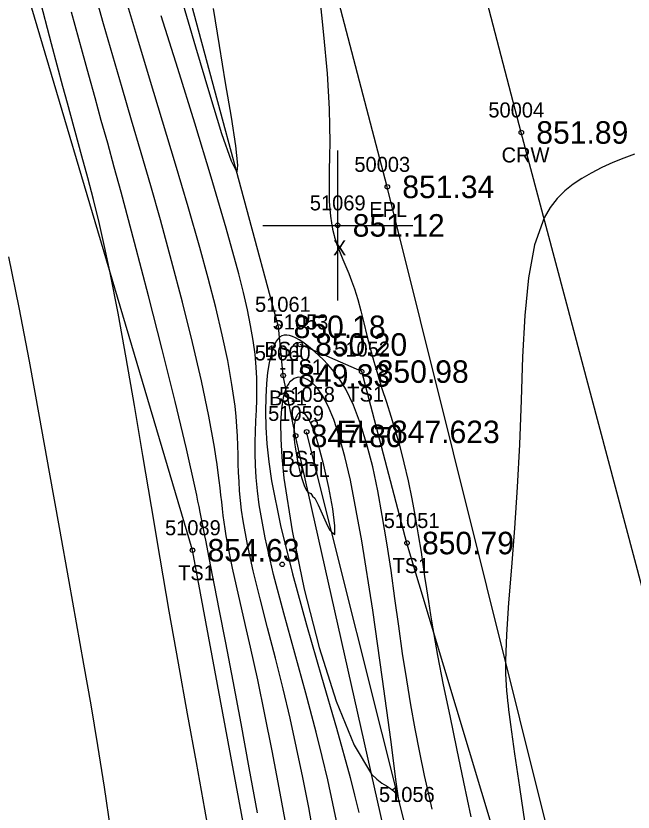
# Model space of a CAD drawing. Extents: x 1378535 to 1380697, y 997729 to 1000024.
# Drawn here: x 1380545.3 to 1380586.5, y 997786.4 to 997839.4 of the extents above; entities that cross this region are included whole.
import ezdxf

# ---------------------------------------------------------------- set-up
doc = ezdxf.new("R2010")
doc.units = 0
for name, color, linetype in [('RD_DTM_BkLn1', 7, 'Continuous'), ('RD_DTM_BkLn2', 7, 'Continuous'), ('RD_DTM_BkLn_txCode', 7, 'Continuous'), ('RD_DTM_Major1', 7, 'Continuous'), ('RD_DTM_Minor1', 7, 'Continuous'), ('RD_EX_H2O', 7, 'Continuous'), ('RD_EX_H2O_txCode', 7, 'Continuous'), ('RD_EX_Misc', 7, 'Continuous'), ('RD_EX_Misc_txCode', 7, 'Continuous'), ('RD_EX_Road', 7, 'Continuous'), ('RD_EX_Road_txCode', 7, 'Continuous'), ('RD_EX_TX_H2O_ELEV', 7, 'Continuous'), ('RD_EX_TX_Misc_ELEV', 7, 'Continuous'), ('RD_EX_TX_Road_ELEV', 7, 'Continuous'), ('RD_HC_Survey_ELEV', 7, 'Continuous'), ('RD_HC_Survey_txCode', 7, 'Continuous'), ('RD_SMD_Locator', 7, 'Continuous')]:
    doc.layers.add(name, color=color, linetype=linetype)

msp = doc.modelspace()

# ---------------------------------------------------------------- linework, layer by layer
at = {"layer": 'RD_DTM_BkLn1'}
msp.add_lwpolyline([(1380595.731, 997768.759), (1380579.003, 997831.65), (1380561.901, 997897.143), (1380561.34, 997899.221)], dxfattribs=at)
at = {"layer": 'RD_DTM_BkLn2'}
for points in [[(1380566.757, 997751.771), (1380557.077, 997803.811), (1380541.168, 997857.405), (1380521.16, 997925.477), (1380502.894, 997980.039), (1380480.452, 998018.575)], [(1380574.915, 997757.623), (1380570.09, 997784.156), (1380563.954, 997811.43), (1380563.127, 997815.458), (1380562.818, 997818.699), (1380551.354, 997861.143), (1380533.627, 997927.476), (1380517.511, 997988.596)], [(1380585.48, 997757.391), (1380571.379, 997804.293), (1380568.36, 997815.716), (1380564.253, 997817.522)]]:
    msp.add_lwpolyline(points, dxfattribs=at)
at = {"layer": 'RD_DTM_Major1'}
for points in [[(1380558.703, 997782.081), (1380557.896, 997786.549), (1380557.332, 997789.658), (1380556.744, 997792.913), (1380556.14, 997796.288), (1380555.529, 997799.755), (1380554.92, 997803.285), (1380554.34, 997806.722), (1380553.771, 997810.132), (1380553.211, 997813.456), (1380552.66, 997816.632), (1380552.119, 997819.601), (1380551.588, 997822.302), (1380551.213, 997824.048), (1380550.84, 997825.661), (1380550.465, 997827.18), (1380550.086, 997828.638), (1380549.7, 997830.074), (1380548.736, 997833.599), (1380548.431, 997834.722), (1380547.675, 997837.559), (1380546.841, 997840.723)], [(1380558.447, 997839.905), (1380558.846, 997837.453), (1380559.263, 997834.966), (1380559.646, 997832.661), (1380559.937, 997830.758), (1380560.083, 997829.474), (1380560.028, 997829.027), (1380559.669, 997829.737), (1380559.042, 997831.561), (1380558.225, 997834.195), (1380557.295, 997837.336), (1380556.327, 997840.681)], [(1380569.716, 997806.133), (1380569.426, 997807.779), (1380569.091, 997809.363), (1380568.71, 997810.859), (1380568.283, 997812.239), (1380567.81, 997813.477), (1380567.29, 997814.545), (1380567.006, 997815.017), (1380566.713, 997815.443), (1380566.413, 997815.828), (1380566.109, 997816.178), (1380565.804, 997816.496), (1380565.501, 997816.789), (1380565.225, 997817.04), (1380564.955, 997817.271), (1380564.691, 997817.481), (1380564.433, 997817.667), (1380564.184, 997817.827), (1380563.944, 997817.958), (1380563.744, 997818.048), (1380563.552, 997818.111), (1380563.369, 997818.142), (1380563.196, 997818.137), (1380563.035, 997818.093), (1380562.884, 997818.003), (1380562.662, 997817.75), (1380562.472, 997817.375), (1380562.314, 997816.891), (1380562.185, 997816.31), (1380562.085, 997815.646), (1380562.011, 997814.912), (1380561.958, 997814.02), (1380561.943, 997813.054), (1380561.969, 997812.014), (1380562.042, 997810.897), (1380562.167, 997809.704), (1380562.35, 997808.432), (1380562.936, 997805.468), (1380563.734, 997802.24), (1380564.672, 997798.847), (1380565.675, 997795.387), (1380566.669, 997791.961), (1380567.582, 997788.666), (1380567.886, 997787.492), (1380568.173, 997786.336)], [(1380573.051, 997786.559), (1380572.893, 997787.266), (1380572.555, 997788.796), (1380572.227, 997790.34), (1380571.916, 997791.909), (1380571.629, 997793.515), (1380571.374, 997795.17), (1380571.086, 997796.936), (1380570.825, 997798.751), (1380570.574, 997800.596), (1380570.317, 997802.454), (1380570.036, 997804.306), (1380569.716, 997806.133)]]:
    msp.add_lwpolyline(points, dxfattribs=at)
at = {"layer": 'RD_DTM_Minor1'}
for points in [[(1380563.314, 997785.481), (1380562.86, 997787.97), (1380562.387, 997790.446), (1380561.905, 997792.866), (1380561.423, 997795.186), (1380560.947, 997797.363), (1380560.618, 997798.808), (1380560.009, 997801.431), (1380559.744, 997802.619), (1380559.513, 997803.73), (1380559.323, 997804.769), (1380559.249, 997805.234), (1380559.184, 997805.688), (1380559.126, 997806.136), (1380559.072, 997806.581), (1380559.021, 997807.03), (1380558.97, 997807.485), (1380558.916, 997807.965), (1380558.859, 997808.461), (1380558.796, 997808.977), (1380558.724, 997809.518), (1380558.642, 997810.087), (1380558.547, 997810.69), (1380558.167, 997812.756), (1380557.668, 997815.101), (1380557.072, 997817.653), (1380556.402, 997820.34), (1380555.682, 997823.089), (1380554.933, 997825.828), (1380554.294, 997828.088), (1380553.654, 997830.3), (1380553.016, 997832.475), (1380552.383, 997834.625), (1380551.758, 997836.761), (1380551.145, 997838.893), (1380550.493, 997841.214)], [(1380565.2, 997784.631), (1380564.825, 997786.664), (1380564.433, 997788.669), (1380564.019, 997790.652), (1380563.583, 997792.616), (1380563.121, 997794.567), (1380562.606, 997796.617), (1380562.084, 997798.631), (1380561.582, 997800.582), (1380561.125, 997802.442), (1380560.738, 997804.185), (1380560.447, 997805.782), (1380560.35, 997806.474), (1380560.275, 997807.134), (1380560.22, 997807.768), (1380560.18, 997808.382), (1380560.151, 997808.982), (1380560.129, 997809.573), (1380560.11, 997810.18), (1380560.091, 997810.79), (1380560.065, 997811.412), (1380560.03, 997812.051), (1380559.98, 997812.714), (1380559.91, 997813.409), (1380559.708, 997814.86), (1380559.421, 997816.445), (1380559.057, 997818.158), (1380558.621, 997819.989), (1380558.121, 997821.932), (1380557.562, 997823.98), (1380556.783, 997826.705), (1380555.948, 997829.531), (1380555.082, 997832.406), (1380554.211, 997835.276), (1380553.361, 997838.087), (1380552.559, 997840.787)], [(1380565.54, 997840.803), (1380565.819, 997838.145), (1380566.048, 997835.582), (1380566.191, 997833.229), (1380566.222, 997832.077), (1380566.225, 997831.016), (1380566.213, 997830.041), (1380566.194, 997829.146), (1380566.18, 997828.326), (1380566.18, 997827.575), (1380566.196, 997827.044), (1380566.227, 997826.546), (1380566.274, 997826.076), (1380566.338, 997825.63), (1380566.421, 997825.203), (1380566.522, 997824.79), (1380566.556, 997824.669), (1380566.592, 997824.549), (1380566.63, 997824.429), (1380566.71, 997824.19), (1380566.752, 997824.071), (1380566.921, 997823.63), (1380567.104, 997823.183), (1380567.297, 997822.724), (1380567.494, 997822.25), (1380567.688, 997821.755), (1380567.874, 997821.236), (1380568.097, 997820.519), (1380568.305, 997819.758), (1380568.507, 997818.959), (1380568.712, 997818.129), (1380568.928, 997817.273), (1380569.163, 997816.398), (1380569.426, 997815.504), (1380569.709, 997814.596), (1380570.003, 997813.675), (1380570.301, 997812.738), (1380570.593, 997811.787), (1380570.871, 997810.821), (1380571.177, 997809.639), (1380571.454, 997808.442), (1380571.704, 997807.239), (1380571.929, 997806.037), (1380572.133, 997804.847), (1380572.318, 997803.674), (1380572.439, 997802.864), (1380572.557, 997802.054), (1380572.677, 997801.232), (1380572.804, 997800.387), (1380572.943, 997799.505), (1380573.098, 997798.574), (1380573.423, 997796.791), (1380573.803, 997794.847), (1380574.227, 997792.772), (1380574.683, 997790.596), (1380575.159, 997788.348), (1380575.643, 997786.057)], [(1380561.416, 997786.316), (1380560.86, 997789.323), (1380560.31, 997792.276), (1380559.782, 997795.082), (1380559.294, 997797.648), (1380558.862, 997799.882), (1380558.567, 997801.375), (1380558.433, 997802.049), (1380558.184, 997803.31), (1380557.955, 997804.488), (1380557.899, 997804.778), (1380557.784, 997805.375), (1380557.724, 997805.685), (1380557.658, 997806.016), (1380557.589, 997806.36), (1380557.517, 997806.717), (1380557.44, 997807.09), (1380557.358, 997807.48), (1380557.27, 997807.888), (1380556.665, 997810.57), (1380555.912, 997813.723), (1380555.056, 997817.179), (1380554.142, 997820.769), (1380553.213, 997824.326), (1380552.315, 997827.679), (1380551.86, 997829.343), (1380551.421, 997830.927), (1380550.994, 997832.457), (1380550.573, 997833.962), (1380550.154, 997835.466), (1380549.731, 997836.997), (1380549.006, 997839.669)], [(1380566.76, 997785.364), (1380566.437, 997786.941), (1380566.094, 997788.504), (1380565.726, 997790.078), (1380565.325, 997791.685), (1380564.631, 997794.288), (1380563.892, 997796.957), (1380563.161, 997799.62), (1380562.487, 997802.203), (1380561.923, 997804.633), (1380561.52, 997806.835), (1380561.399, 997807.771), (1380561.319, 997808.648), (1380561.272, 997809.474), (1380561.254, 997810.257), (1380561.257, 997811.004), (1380561.276, 997811.722), (1380561.304, 997812.438), (1380561.335, 997813.142), (1380561.36, 997813.842), (1380561.372, 997814.548), (1380561.364, 997815.269), (1380561.328, 997816.013), (1380561.247, 997816.878), (1380561.121, 997817.795), (1380560.95, 997818.777), (1380560.732, 997819.834), (1380560.467, 997820.98), (1380560.154, 997822.224), (1380559.319, 997825.267), (1380558.32, 997828.668), (1380557.222, 997832.269), (1380556.091, 997835.908), (1380554.992, 997839.427)], [(1380586.551, 997830.207), (1380585.835, 997829.941), (1380585.107, 997829.64), (1380584.378, 997829.305), (1380583.659, 997828.938), (1380583.047, 997828.591), (1380582.458, 997828.204), (1380581.903, 997827.763), (1380581.389, 997827.251), (1380580.925, 997826.652), (1380580.519, 997825.951), (1380579.886, 997824.165), (1380579.476, 997821.971), (1380579.23, 997819.455), (1380579.09, 997816.706), (1380578.996, 997813.811), (1380578.891, 997810.859), (1380578.736, 997808.024), (1380578.543, 997805.279), (1380578.339, 997802.686), (1380578.154, 997800.307), (1380578.015, 997798.203), (1380577.949, 997796.437), (1380577.948, 997795.998), (1380577.955, 997795.586), (1380577.969, 997795.194), (1380577.991, 997794.814), (1380578.019, 997794.439), (1380578.054, 997794.064), (1380578.084, 997793.773), (1380578.118, 997793.477), (1380578.155, 997793.172), (1380578.195, 997792.857), (1380578.238, 997792.531), (1380578.284, 997792.191), (1380578.558, 997790.248), (1380578.883, 997788.02), (1380579.236, 997785.609)], [(1380551.622, 997785.135), (1380551.208, 997788.018), (1380550.771, 997790.796), (1380550.313, 997793.513), (1380549.837, 997796.212), (1380548.839, 997801.73), (1380548.198, 997805.32), (1380547.543, 997809.011), (1380546.875, 997812.731), (1380546.198, 997816.41), (1380545.511, 997819.979), (1380544.819, 997823.364)], [(1380570.804, 997787.289), (1380570.657, 997788.371), (1380570.292, 997791.21), (1380569.756, 997795.223), (1380569.097, 997799.828), (1380568.363, 997804.439), (1380567.601, 997808.474), (1380567.233, 997810.069), (1380566.866, 997811.41), (1380566.499, 997812.519), (1380566.127, 997813.416), (1380565.747, 997814.123), (1380565.357, 997814.66), (1380565.046, 997814.972), (1380564.733, 997815.191), (1380564.426, 997815.313), (1380564.132, 997815.335), (1380563.858, 997815.254), (1380563.61, 997815.066), (1380563.554, 997815.003), (1380563.5, 997814.933), (1380563.448, 997814.856), (1380563.399, 997814.772), (1380563.352, 997814.681), (1380563.307, 997814.582), (1380563.125, 997813.996), (1380563.006, 997813.24), (1380562.949, 997812.319), (1380562.958, 997811.238), (1380563.033, 997810.003), (1380563.174, 997808.619), (1380563.718, 997805.105), (1380564.527, 997801.229), (1380565.531, 997797.331), (1380566.661, 997793.749), (1380567.848, 997790.825), (1380569.023, 997788.898), (1380569.372, 997788.55), (1380569.703, 997788.296), (1380570.007, 997788.104), (1380570.274, 997787.939), (1380570.495, 997787.769), (1380570.66, 997787.56), (1380570.702, 997787.498), (1380570.736, 997787.433), (1380570.762, 997787.373), (1380570.781, 997787.324), (1380570.795, 997787.293), (1380570.804, 997787.289)], [(1380566.362, 997805.015), (1380566.571, 997804.854), (1380566.575, 997805.446), (1380566.423, 997806.565), (1380566.16, 997807.984), (1380565.832, 997809.476), (1380565.486, 997810.815), (1380565.323, 997811.349), (1380565.168, 997811.798), (1380565.018, 997812.167), (1380564.875, 997812.461), (1380564.738, 997812.687), (1380564.606, 997812.848), (1380564.507, 997812.932), (1380564.413, 997812.982), (1380564.323, 997812.999), (1380564.238, 997812.984), (1380564.16, 997812.939), (1380564.087, 997812.866), (1380564.026, 997812.771), (1380563.972, 997812.652), (1380563.926, 997812.511), (1380563.889, 997812.348), (1380563.862, 997812.164), (1380563.845, 997811.96), (1380563.84, 997811.735), (1380563.846, 997811.493), (1380563.861, 997811.237), (1380563.887, 997810.969), (1380563.92, 997810.692), (1380563.962, 997810.408), (1380564.078, 997809.771), (1380564.219, 997809.154), (1380564.372, 997808.593), (1380564.529, 997808.129), (1380564.677, 997807.8), (1380564.806, 997807.644), (1380564.841, 997807.634), (1380564.876, 997807.631), (1380564.915, 997807.622), (1380564.96, 997807.592), (1380565.014, 997807.529), (1380565.081, 997807.419), (1380565.224, 997807.284), (1380565.448, 997806.839), (1380565.713, 997806.237), (1380565.98, 997805.63), (1380566.209, 997805.172), (1380566.362, 997805.015)]]:
    msp.add_lwpolyline(points, dxfattribs=at)
at = {"layer": 'RD_EX_H2O'}
msp.add_lwpolyline([(1380575.586, 997758.064), (1380571.368, 997785.038), (1380564.688, 997811.698)], dxfattribs=at)
at = {"layer": 'RD_EX_Misc'}
for p, q in [((1380566.759, 997820.458), (1380566.759, 997830.458)), ((1380561.759, 997825.458), (1380571.759, 997825.458))]:
    msp.add_line(p, q, dxfattribs=at)
at = {"layer": 'RD_EX_Road'}
msp.add_lwpolyline([(1380585.558, 997765.946), (1380570.067, 997828.024), (1380552.38, 997895.514), (1380551.892, 997897.33)], dxfattribs=at)
at = {"layer": 'RD_SMD_Locator'}
for centre, radius in [((1380579.003, 997831.65), 0.15), ((1380570.067, 997828.024), 0.15), ((1380566.759, 997825.458), 0.15), ((1380562.818, 997818.699), 0.15), ((1380564.253, 997817.522), 0.15), ((1380568.36, 997815.716), 0.15), ((1380563.127, 997815.458), 0.15), ((1380565.198, 997812.257), 0.2), ((1380563.954, 997811.43), 0.15), ((1380564.688, 997811.698), 0.15), ((1380571.379, 997804.293), 0.15), ((1380557.077, 997803.811), 0.15), ((1380563.059, 997802.875), 0.15)]:
    msp.add_circle(centre, radius, dxfattribs=at)

# ---------------------------------------------------------------- texts
at = {"layer": 'RD_DTM_BkLn_txCode'}
for s, p in [('51061', (1380561.243, 997819.699)), ('51053', (1380562.418, 997818.522)), ('51060', (1380561.229, 997816.458)), ('BS1', (1380561.873, 997816.699)), ('51052', (1380566.525, 997816.716)), ('-TS1', (1380562.883, 997815.522)), ('TS1', (1380567.399, 997813.716)), ('BS1', (1380562.182, 997813.458)), ('51059', (1380562.119, 997812.43)), ('BS1', (1380563.009, 997809.43)), ('51051', (1380569.828, 997805.293)), ('51089', (1380555.242, 997804.811)), ('TS1', (1380570.418, 997802.293)), ('TS1', (1380556.116, 997801.811))]:
    msp.add_text(s, height=1, dxfattribs=at).set_placement(p)
at = {"layer": 'RD_EX_H2O_txCode'}
for s, p in [('51058', (1380562.853, 997813.698)), ('-ODL', (1380563.034, 997808.698)), ('51056', (1380569.51, 997787.038))]:
    msp.add_text(s, height=1, dxfattribs=at).set_placement(p)
at = {"layer": 'RD_EX_Misc_txCode'}
for s, p in [('51069', (1380564.901, 997826.458)), ('X', (1380566.444, 997823.458))]:
    msp.add_text(s, height=1, dxfattribs=at).set_placement(p)
at = {"layer": 'RD_EX_Road_txCode'}
for s, p in [('50003', (1380567.87, 997829.024)), ('EPL', (1380568.862, 997826.024))]:
    msp.add_text(s, height=1, dxfattribs=at).set_placement(p)
at = {"layer": 'RD_EX_TX_H2O_ELEV'}
msp.add_text('EL=847.623', height=1.5, dxfattribs=at).set_placement((1380566.688, 997810.948))
at = {"layer": 'RD_EX_TX_Misc_ELEV'}
for s, p in [('851.12', (1380567.759, 997824.708)), ('850.18', (1380563.818, 997817.949)), ('850.20', (1380565.253, 997816.772)), ('850.98', (1380569.36, 997814.966)), ('849.33', (1380564.127, 997814.708)), ('847.80', (1380564.954, 997810.68)), ('854.63', (1380558.077, 997803.061)), ('850.79', (1380572.379, 997803.543))]:
    msp.add_text(s, height=1.5, dxfattribs=at).set_placement(p)
at = {"layer": 'RD_EX_TX_Road_ELEV'}
msp.add_text('851.34', height=1.5, dxfattribs=at).set_placement((1380571.067, 997827.274))
at = {"layer": 'RD_HC_Survey_ELEV'}
msp.add_text('851.89', height=1.5, dxfattribs=at).set_placement((1380580.003, 997830.9))
at = {"layer": 'RD_HC_Survey_txCode'}
for s, p in [('50004', (1380576.806, 997832.65)), ('CRW', (1380577.688, 997829.65))]:
    msp.add_text(s, height=1, dxfattribs=at).set_placement(p)

doc.saveas('drawing.dxf')
